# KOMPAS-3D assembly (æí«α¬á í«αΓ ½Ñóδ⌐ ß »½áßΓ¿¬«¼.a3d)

Referenced files in D:\МОДЕЛЬ ТАНКА Т90\СБОРКИ\СБОРКА ЛИТЬЕ СТАРАЯ\: Сборка борт левый.a3d
Referenced files in D:\МОДЕЛЬ ТАНКА Т90\ДЕТАЛИ\КОРПУС\МЕТАЛЛ\КОРПУС ШТАМПОВКА\ПЛАСТИК\: борт пластик левый.m3d
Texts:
  Сборка борт левый с пластиком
